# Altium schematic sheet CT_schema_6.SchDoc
size 218 x 258 mm
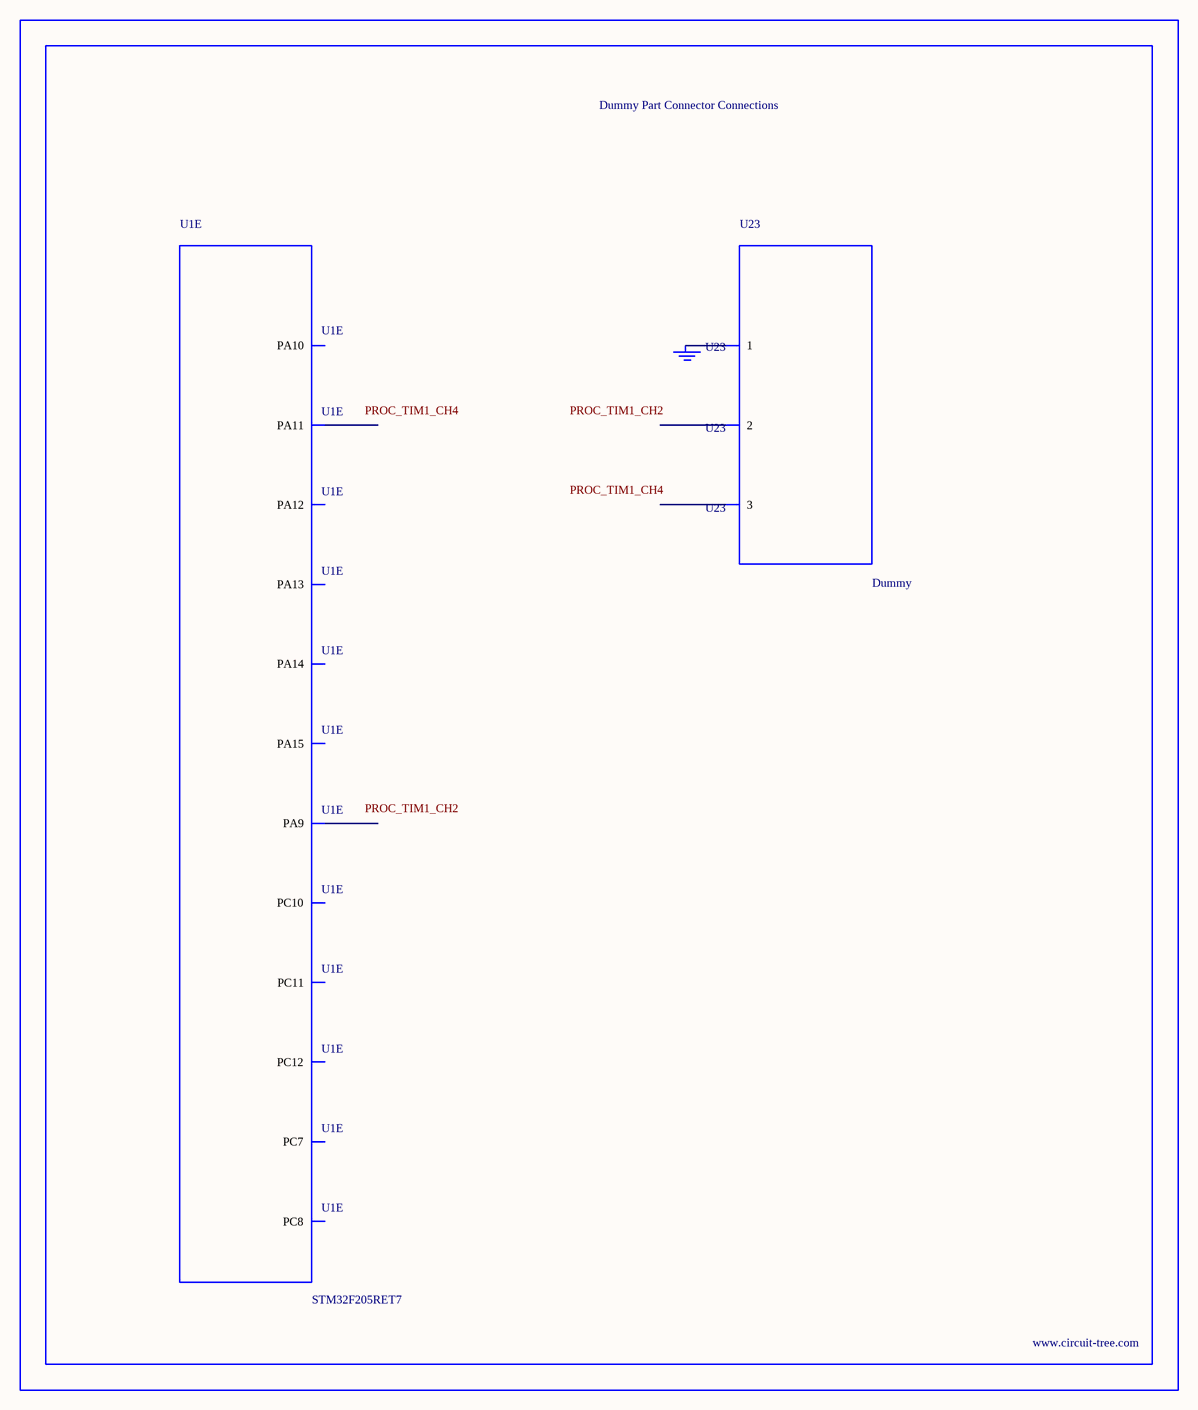
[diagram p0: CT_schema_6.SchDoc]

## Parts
BORDER5  (no value)
GND_INSTANCE_5_0  (no value)
U1  STM32F205RET7  [LQFP64]  (part E of 5)
U23  Dummy  [DUMMY_PACKAGE_217]

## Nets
NetGND_INSTANCE_5_0_0: GND_INSTANCE_5_0.0(GND) U23.1

Not connected (* = marked no-connect by the designer): U1 38(PC7) 39(PC8) 42(PA9) 43(PA10) 44(PA11) 45(PA12) 46(PA13) 49(PA14) 50(PA15) 51(PC10) 52(PC11) 53(PC12); U23 2 3

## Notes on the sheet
- Labels drawn without touching a wire or pin: PROC_TIM1_CH2, PROC_TIM1_CH4

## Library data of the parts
BORDER5 = BORDER_PAGE5
GND_INSTANCE_5_0 = GND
